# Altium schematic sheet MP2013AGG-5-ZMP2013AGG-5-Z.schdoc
size 127 x 101 mm
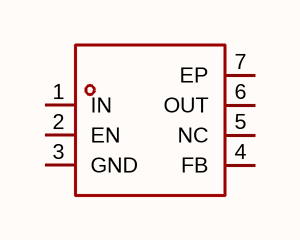
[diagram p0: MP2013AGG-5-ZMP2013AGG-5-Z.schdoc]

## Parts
U?  mp2013agg-5-z  [QFN-6_L2.0-W2.0-P0.65-TL-EP]  (value not drawn)

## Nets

Not connected (* = marked no-connect by the designer): U? 1(IN) 2(EN) 3(GND) 4(FB) 5(NC) 6(OUT) 7(EP)

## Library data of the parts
U? = mp2013agg-5-z: 输出极性:正极;工作电压:40V;输出电压:5V;输出电流:150mA;电源纹波抑制比(PSRR):58dB@(100Hz);输出类型:固定;; Manufacturer: MPS(芯源); AddInBom: yes; ModelId: fb954096014f4050b0970d73f1ef6cc4; ModelName: QFN-6_L2.0-W2.0-H0.8-P0.65; ModelTransform: 78.74,77.961,0,0,0,0,0.0005,0,0; Output Configuration: 正极; Voltage - Supply: 40V; Output Voltage: 5V; Output Current: 150mA; Voltage Dropout: 600mV@(150mA); standby current: 4.4uA; Output Type: 固定; Number of Outputs: 1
